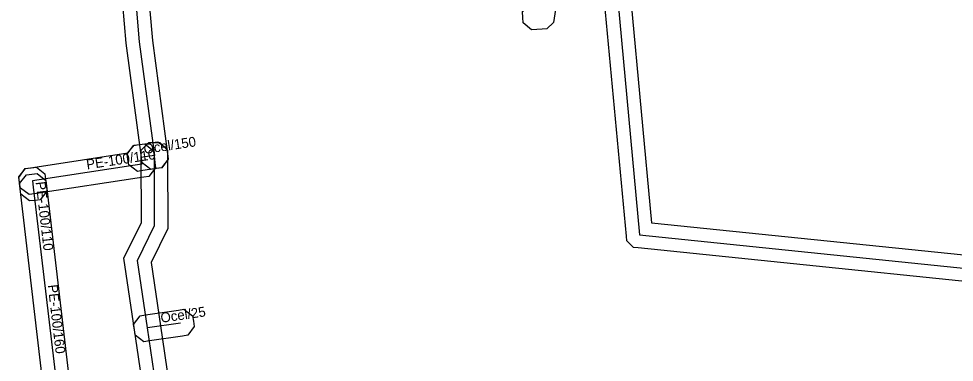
# Model space of a CAD drawing. Extents: x -569373 to -565022, y -1135090 to -1131496.
# Drawn here: x -565662.5 to -565591.3, y -1133296 to -1133269.9 of the extents above; entities that cross this region are included whole.
import ezdxf

# ---------------------------------------------------------------- set-up
doc = ezdxf.new("R2010")
doc.units = 0
for name, color, linetype in [('1', 7, 'Continuous'), ('24', 7, 'Continuous'), ('30', 7, 'Continuous'), ('55', 7, 'Continuous'), ('7', 7, 'Continuous')]:
    doc.layers.add(name, color=color, linetype=linetype)

msp = doc.modelspace()

# ---------------------------------------------------------------- linework, layer by layer
at = {"layer": '1'}
for points in [[(-565623.628, -1133268.734), (-565623.609, -1133268.733), (-565621.549, -1133255.249), (-565621.486, -1133254.839), (-565620.819, -1133254.348), (-565620.409, -1133254.411), (-565619.999, -1133254.474), (-565619.508, -1133255.141), (-565619.571, -1133255.551), (-565621.751, -1133269.821), (-565621.804, -1133270.166), (-565622.317, -1133270.641), (-565622.665, -1133270.667), (-565623.065, -1133270.697), (-565623.478, -1133270.728), (-565624.106, -1133270.188), (-565624.137, -1133269.775), (-565624.168, -1133269.362)], [(-565651.61, -1133281.227), (-565652.02, -1133281.289), (-565652.547, -1133281.369), (-565653.041, -1133281.444), (-565653.451, -1133281.506), (-565654.118, -1133281.015), (-565654.18, -1133280.605), (-565654.242, -1133280.195), (-565653.751, -1133279.528), (-565653.341, -1133279.466), (-565652.847, -1133279.391), (-565652.32, -1133279.311), (-565651.91, -1133279.249), (-565651.243, -1133279.74), (-565651.181, -1133280.15), (-565651.119, -1133280.56)], [(-565661.098, -1133281.153), (-565654.185, -1133280.1), (-565653.718, -1133279.51), (-565653.307, -1133279.462), (-565652.896, -1133279.414), (-565652.246, -1133279.928), (-565652.198, -1133280.339), (-565652.14, -1133280.836), (-565652.093, -1133281.237), (-565652.583, -1133281.88), (-565652.982, -1133281.941), (-565653.481, -1133282.017), (-565660.798, -1133283.131), (-565661.292, -1133283.206), (-565661.702, -1133283.268), (-565662.369, -1133282.777), (-565662.431, -1133282.367), (-565662.493, -1133281.957), (-565662.002, -1133281.29), (-565661.592, -1133281.228)], [(-565660.497, -1133281.69), (-565660.449, -1133282.101), (-565660.391, -1133282.598), (-565660.343, -1133283.009), (-565660.857, -1133283.659), (-565661.268, -1133283.707), (-565661.679, -1133283.755), (-565662.329, -1133283.241), (-565662.377, -1133282.83), (-565662.435, -1133282.333), (-565662.483, -1133281.922), (-565661.969, -1133281.272), (-565661.558, -1133281.224), (-565661.147, -1133281.176)], [(-565660.439, -1133282.186), (-565660.391, -1133282.598), (-565658.611, -1133297.794), (-565658.563, -1133298.205), (-565659.076, -1133298.855), (-565659.488, -1133298.903), (-565659.899, -1133298.951), (-565660.549, -1133298.438), (-565660.597, -1133298.026), (-565662.377, -1133282.83), (-565662.425, -1133282.419), (-565661.912, -1133281.769), (-565661.5, -1133281.721), (-565661.089, -1133281.673)], [(-565649.634, -1133293.979), (-565650.044, -1133294.039), (-565652.554, -1133294.409), (-565652.964, -1133294.469), (-565653.629, -1133293.976), (-565653.689, -1133293.566), (-565653.749, -1133293.156), (-565653.256, -1133292.491), (-565652.846, -1133292.431), (-565650.336, -1133292.061), (-565649.926, -1133292.001), (-565649.261, -1133292.494), (-565649.201, -1133292.904), (-565649.141, -1133293.314)]]:
    msp.add_lwpolyline(points, close=True, dxfattribs=at)
for points in [[(-565652.887, -1133265.021), (-565652.326, -1133271.531), (-565651.179, -1133280.168), (-565651.124, -1133280.579), (-565651.628, -1133281.237), (-565652.038, -1133281.291), (-565652.449, -1133281.346), (-565653.107, -1133280.842), (-565653.161, -1133280.432), (-565654.314, -1133271.749), (-565654.953, -1133264.339)], [(-565646.525, -1133345.02), (-565647.384, -1133335.429), (-565649.67, -1133329.486), (-565649.67, -1133329.321), (-565653.062, -1133297.866), (-565653.689, -1133293.565), (-565654.495, -1133288.118), (-565653.151, -1133285.389), (-565653.17, -1133280.304), (-565653.172, -1133279.89), (-565652.588, -1133279.302), (-565652.174, -1133279.3), (-565651.76, -1133279.298), (-565651.172, -1133279.882), (-565651.17, -1133280.296), (-565651.149, -1133285.851), (-565652.425, -1133288.442), (-565651.711, -1133293.275), (-565651.078, -1133297.614), (-565647.685, -1133329.076), (-565645.416, -1133334.971), (-565644.535, -1133344.82)]]:
    msp.add_lwpolyline(points, dxfattribs=at)
at = {"layer": '24'}
for points in [[(-565623.24, -1133253.2), (-565623.38, -1133255.02), (-565639.59, -1133252.32), (-565641.56, -1133260.72), (-565650.05, -1133260.3), (-565653.92, -1133264.68), (-565653.32, -1133271.64), (-565652.17, -1133280.3)], [(-565653.191, -1133280.455), (-565653.133, -1133280.952), (-565653.632, -1133281.028), (-565660.948, -1133282.142), (-565661.442, -1133282.217)], [(-565632.13, -1133459.49), (-565635.18, -1133435.22), (-565636.392, -1133425.015), (-565638.801, -1133404.72), (-565639.7, -1133397.15), (-565643.15, -1133366.24), (-565644.64, -1133352.93), (-565645.53, -1133344.92), (-565646.4, -1133335.2), (-565648.67, -1133329.3), (-565648.67, -1133329.27), (-565652.07, -1133297.74), (-565652.7, -1133293.42), (-565653.46, -1133288.28), (-565652.15, -1133285.62), (-565652.17, -1133280.3)], [(-565652.17, -1133280.3), (-565652.697, -1133280.38), (-565653.191, -1133280.455)], [(-565661.442, -1133282.217), (-565661.384, -1133282.714)], [(-565661.384, -1133282.714), (-565659.604, -1133297.91)], [(-565650.19, -1133293.05), (-565652.7, -1133293.42)]]:
    msp.add_lwpolyline(points, dxfattribs=at)
at = {"layer": '55'}
msp.add_lwpolyline([(-565634.64, -1133251.55), (-565634.65, -1133251.91), (-565620.23, -1133254.35), (-565617.27, -1133261.77), (-565616.92, -1133268.5), (-565615.26, -1133286.34), (-565577.34, -1133290.23), (-565547.83, -1133294.34), (-565523.25, -1133295.46)], dxfattribs=at)
at = {"layer": '7'}
for points in [[(-565577.46, -1133291.223), (-565615.362, -1133287.335), (-565615.719, -1133287.298), (-565616.223, -1133286.79), (-565616.256, -1133286.433), (-565617.918, -1133268.572)], [(-565615.922, -1133268.428), (-565614.34, -1133285.429), (-565577.22, -1133289.237)]]:
    msp.add_lwpolyline(points, dxfattribs=at)

# ---------------------------------------------------------------- texts
at = {"layer": '30'}
for s, rotation, p in [('Ocel/150', 8.63175, (-565652.93, -1133280.185)), ('PE-100/110', 8.65787, (-565657.29, -1133281.354)), ('PE-100/110', 276.65632, (-565661.207, -1133282.315)), ('PE-100/160', 276.68096, (-565660.288, -1133290.162)), ('Ocel/25', 8.3856, (-565651.645, -1133293.035))]:
    msp.add_text(s, height=0.75, rotation=rotation, dxfattribs=at).set_placement(p)

doc.saveas('drawing.dxf')
